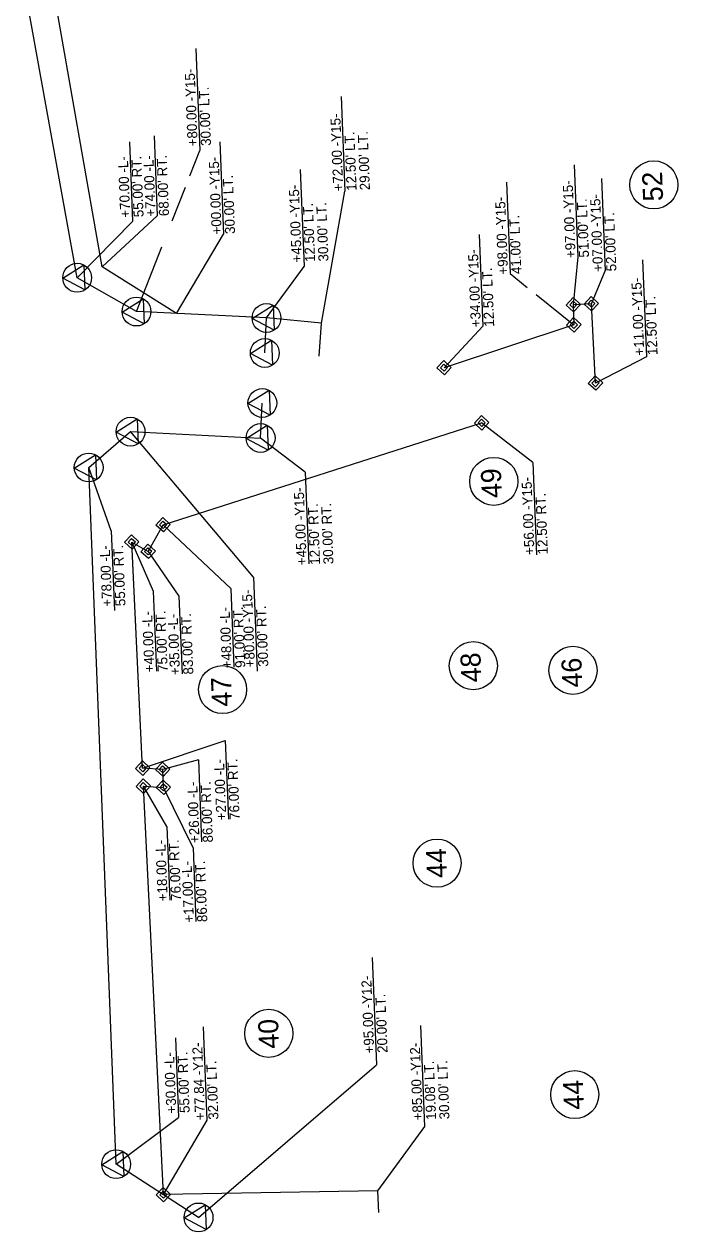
# Model space of a CAD drawing. Extents: x 1627970 to 1628801, y 761752 to 765698.
# Drawn here: x 1628397 to 1628723, y 764572 to 765175 of the extents above; entities that cross this region are included whole.
import ezdxf

# ---------------------------------------------------------------- set-up
doc = ezdxf.new("R2010")
doc.units = 0
for name, color, linetype in [('Exist Property Line Leader', 7, 'Continuous'), ('Exist Property Line Text', 7, 'Continuous'), ('Exist Right of Way Control of Access Line', 7, 'Continuous'), ('Exist Right of Way Monument Leader', 7, 'Continuous'), ('Exist Right of Way Monument Text', 7, 'Continuous'), ('Exist Roads EOT', 7, 'Continuous'), ('Exist Utilities Gas UG Line', 7, 'Continuous'), ('Exist Utilities Gas UG Line Text', 7, 'Continuous'), ('Exist Utilities Other Unknown UG SUE Text', 7, 'Continuous')]:
    doc.layers.add(name, color=color, linetype=linetype)

msp = doc.modelspace()

# ---------------------------------------------------------------- linework, layer by layer
at = {"layer": 'Exist Property Line Leader'}
for p, q in [((1628679.79, 765035.16), (1628670.77, 765034.66)), ((1628670.77, 765034.66), (1628671.03, 765024.62)), ((1628681.86, 764995.53), (1628679.79, 765035.16)), ((1628671.03, 765024.62), (1628606.25, 765003.22)), ((1628625.64, 765023.98), (1628606.25, 765003.22)), ((1628465.98, 764924.84), (1628625.01, 764975.71)), ((1628458.5, 764911.53), (1628465.98, 764924.84)), ((1628455.76, 764803.34), (1628450.31, 764916.21)), ((1628450.31, 764916.21), (1628458.5, 764911.53)), ((1628465.8, 764802.74), (1628455.76, 764803.34)), ((1628466.15, 764793.74), (1628465.8, 764802.74)), ((1628466.1, 764590.44), (1628456.12, 764794.35)), ((1628456.12, 764794.35), (1628466.15, 764793.74))]:
    msp.add_line(p, q, dxfattribs=at)
at = {"layer": 'Exist Property Line Text'}
for p, q in [((1628710.97, 765094.48), (1628710.97, 765094.48)), ((1628631.08, 764946.47), (1628631.08, 764946.47)), ((1628620.87, 764854.47), (1628620.87, 764854.47)), ((1628670.61, 764852.15), (1628670.61, 764852.15)), ((1628495.67, 764842.56), (1628495.67, 764842.56)), ((1628602.74, 764755.93), (1628602.74, 764755.93)), ((1628518.74, 764670.96), (1628518.74, 764670.96)), ((1628671.51, 764640.38), (1628671.51, 764640.38))]:
    msp.add_line(p, q, dxfattribs=at)
for centre in [(1628710.97, 765094.48), (1628631.08, 764946.47), (1628620.87, 764854.47), (1628670.61, 764852.15), (1628495.67, 764842.56), (1628602.74, 764755.93), (1628518.74, 764670.96), (1628671.51, 764640.38)]:
    msp.add_circle(centre, 12, dxfattribs=at)
at = {"layer": 'Exist Right of Way Control of Access Line'}
for p, q in [((1628423.08, 765048.13), (1628396.6, 765194.98)), ((1628452.68, 765031.24), (1628423.08, 765048.13)), ((1628517.6, 765028.05), (1628452.68, 765031.24)), ((1628516.74, 765010.57), (1628517.6, 765028.05)), ((1628514.65, 764968.12), (1628515.51, 764985.6)), ((1628428.83, 764953.4), (1628449.73, 764971.31)), ((1628449.73, 764971.31), (1628514.65, 764968.12)), ((1628442.54, 764605.67), (1628428.83, 764953.4)), ((1628483.68, 764579.07), (1628442.54, 764605.67))]:
    msp.add_line(p, q, dxfattribs=at)
at = {"layer": 'Exist Right of Way Monument Leader'}
for points in [[(1628667.18, 765034.52), (1628670.63, 765038.26), (1628674.37, 765034.8), (1628670.92, 765031.06)], [(1628668.98, 765034.59), (1628670.7, 765036.46), (1628672.57, 765034.73), (1628670.85, 765032.86)], [(1628676.19, 765035.01), (1628679.65, 765038.75), (1628683.38, 765035.3), (1628679.93, 765031.56)], [(1628677.99, 765035.08), (1628679.72, 765036.95), (1628681.59, 765035.23), (1628679.86, 765033.36)], [(1628667.43, 765024.48), (1628670.89, 765028.22), (1628674.63, 765024.76), (1628671.17, 765021.03)], [(1628669.23, 765024.55), (1628670.96, 765026.42), (1628672.83, 765024.69), (1628671.1, 765022.82)], [(1628602.65, 765003.08), (1628606.1, 765006.82), (1628609.84, 765003.36), (1628606.39, 764999.62)], [(1628604.45, 765003.15), (1628606.18, 765005.02), (1628608.04, 765003.29), (1628606.32, 765001.42)], [(1628678.27, 764995.39), (1628681.72, 764999.13), (1628685.46, 764995.68), (1628682.01, 764991.94)], [(1628680.07, 764995.46), (1628681.79, 764997.33), (1628683.66, 764995.6), (1628681.93, 764993.74)], [(1628621.41, 764975.57), (1628624.87, 764979.31), (1628628.61, 764975.85), (1628625.15, 764972.11)], [(1628623.21, 764975.64), (1628624.94, 764977.51), (1628626.81, 764975.78), (1628625.08, 764973.91)], [(1628462.39, 764924.7), (1628465.84, 764928.43), (1628469.58, 764924.98), (1628466.13, 764921.24)], [(1628464.19, 764924.77), (1628465.91, 764926.64), (1628467.78, 764924.91), (1628466.06, 764923.04)], [(1628446.72, 764916.07), (1628450.17, 764919.81), (1628453.91, 764916.36), (1628450.45, 764912.62)], [(1628448.51, 764916.14), (1628450.24, 764918.01), (1628452.11, 764916.28), (1628450.38, 764914.41)], [(1628454.91, 764911.39), (1628458.36, 764915.13), (1628462.1, 764911.67), (1628458.65, 764907.94)], [(1628456.7, 764911.46), (1628458.43, 764913.33), (1628460.3, 764911.6), (1628458.57, 764909.73)], [(1628452.17, 764803.2), (1628455.62, 764806.94), (1628459.36, 764803.48), (1628455.91, 764799.74)], [(1628453.97, 764803.27), (1628455.69, 764805.14), (1628457.56, 764803.41), (1628455.84, 764801.54)], [(1628462.2, 764802.59), (1628465.65, 764806.33), (1628469.39, 764802.88), (1628465.94, 764799.14)], [(1628464, 764802.66), (1628465.72, 764804.53), (1628467.59, 764802.81), (1628465.87, 764800.94)], [(1628452.52, 764794.21), (1628455.98, 764797.94), (1628459.72, 764794.49), (1628456.26, 764790.75)], [(1628454.32, 764794.28), (1628456.05, 764796.15), (1628457.92, 764794.42), (1628456.19, 764792.55)], [(1628462.55, 764793.6), (1628466.01, 764797.34), (1628469.75, 764793.88), (1628466.29, 764790.15)], [(1628464.35, 764793.67), (1628466.08, 764795.54), (1628467.95, 764793.81), (1628466.22, 764791.94)], [(1628462.5, 764590.3), (1628465.95, 764594.04), (1628469.69, 764590.58), (1628466.24, 764586.84)], [(1628464.3, 764590.37), (1628466.02, 764592.24), (1628467.89, 764590.51), (1628466.17, 764588.64)]]:
    msp.add_lwpolyline(points, close=True, dxfattribs=at)
at = {"layer": 'Exist Right of Way Monument Text'}
for p, q in [((1628435.63, 765053.51), (1628402.42, 765242.34)), ((1628472.66, 765030.26), (1628435.63, 765053.51)), ((1628545.08, 765025.42), (1628517.6, 765028.05)), ((1628543.94, 765008.96), (1628545.08, 765025.42)), ((1628573.25, 764592.36), (1628466.1, 764590.44)), ((1628573.65, 764581.45), (1628573.25, 764592.36))]:
    msp.add_line(p, q, dxfattribs=at)
at = {"layer": 'Exist Roads EOT'}
for p, q in [((1628671.15, 765104.52), (1628672.96, 765058.5)), ((1628637.43, 765095.91), (1628639.23, 765050.25)), ((1628684.82, 765097.63), (1628686.63, 765051.62)), ((1628623.84, 765069.65), (1628625.64, 765023.98)), ((1628672.96, 765058.5), (1628670.77, 765034.66)), ((1628679.79, 765035.16), (1628686.63, 765051.62)), ((1628705.35, 765057), (1628707.25, 765008.69)), ((1628639.23, 765050.25), (1628647.82, 765043.33)), ((1628652.25, 765039.76), (1628671.03, 765024.62)), ((1628707.25, 765008.69), (1628681.86, 764995.53)), ((1628650.61, 764955.97), (1628625.01, 764975.71)), ((1628650.61, 764955.97), (1628652.43, 764909.84)), ((1628465.98, 764924.84), (1628499.81, 764893)), ((1628450.31, 764916.21), (1628461.07, 764891.66)), ((1628458.5, 764911.53), (1628473.9, 764889.16)), ((1628461.07, 764891.66), (1628462.65, 764851.72)), ((1628473.9, 764889.16), (1628475.43, 764850.37)), ((1628499.81, 764893), (1628501.36, 764853.7)), ((1628455.76, 764803.34), (1628497.01, 764817.06)), ((1628497.01, 764817.06), (1628498.55, 764777.82)), ((1628483.58, 764807.41), (1628465.8, 764802.74)), ((1628483.58, 764807.41), (1628485.2, 764766.51)), ((1628467.83, 764774.18), (1628456.12, 764794.35)), ((1628480.93, 764763.55), (1628466.15, 764793.74)), ((1628467.83, 764774.18), (1628469.28, 764737.43)), ((1628480.93, 764763.55), (1628482.38, 764726.8)), ((1628488.04, 764627.69), (1628486.13, 764674.23)), ((1628466.1, 764590.44), (1628488.04, 764627.69))]:
    msp.add_line(p, q, dxfattribs=at)
at = {"layer": 'Exist Utilities Gas UG Line'}
for p, q in [((1628482.35, 765162.52), (1628484.35, 765111.71)), ((1628449.14, 765115.9), (1628450.71, 765076.12)), ((1628479.32, 765098.93), (1628484.35, 765111.71)), ((1628534.44, 765102.13), (1628536.35, 765053.75)), ((1628470.53, 765076.59), (1628477.12, 765093.33)), ((1628423.08, 765048.13), (1628450.71, 765076.12)), ((1628452.68, 765031.24), (1628465.4, 765063.55)), ((1628517.6, 765028.05), (1628536.35, 765053.75)), ((1628511.11, 764898.7), (1628449.73, 764971.31)), ((1628536.93, 764951.15), (1628514.65, 764968.12)), ((1628440.08, 764921.73), (1628428.83, 764953.4)), ((1628536.93, 764951.15), (1628538.74, 764905.29)), ((1628440.08, 764921.73), (1628441.65, 764881.95)), ((1628511.11, 764898.7), (1628512.97, 764851.67)), ((1628570.38, 764708.85), (1628572.49, 764655.29)), ((1628472.17, 764668.75), (1628473.74, 764628.97)), ((1628483.68, 764579.07), (1628572.49, 764655.29)), ((1628442.54, 764605.67), (1628473.74, 764628.97))]:
    msp.add_line(p, q, dxfattribs=at)
at = {"layer": 'Exist Utilities Gas UG Line Text'}
for p, q in [((1628554.92, 765138.64), (1628556.78, 765091.4)), ((1628461.46, 765118.97), (1628463.03, 765079.1)), ((1628494.29, 765116.03), (1628496.11, 765069.84)), ((1628545.08, 765025.42), (1628556.78, 765091.4)), ((1628435.63, 765053.51), (1628463.03, 765079.1)), ((1628472.66, 765030.26), (1628496.11, 765069.84)), ((1628596.66, 764624.48), (1628594.6, 764674.8)), ((1628573.25, 764592.36), (1628596.66, 764624.48))]:
    msp.add_line(p, q, dxfattribs=at)
at = {"layer": 'Exist Utilities Other Unknown UG SUE Text'}
for p, q in [((1628423.08, 765048.13), (1628423.08, 765048.13)), ((1628670.77, 765034.66), (1628670.77, 765034.66)), ((1628679.79, 765035.16), (1628679.79, 765035.16)), ((1628452.68, 765031.24), (1628452.68, 765031.24)), ((1628517.6, 765028.05), (1628517.6, 765028.05)), ((1628671.03, 765024.62), (1628671.03, 765024.62)), ((1628516.74, 765010.57), (1628516.74, 765010.57)), ((1628606.25, 765003.22), (1628606.25, 765003.22)), ((1628681.86, 764995.53), (1628681.86, 764995.53)), ((1628515.51, 764985.6), (1628515.51, 764985.6)), ((1628625.01, 764975.71), (1628625.01, 764975.71)), ((1628449.73, 764971.31), (1628449.73, 764971.31)), ((1628514.65, 764968.12), (1628514.65, 764968.12)), ((1628428.83, 764953.4), (1628428.83, 764953.4)), ((1628465.98, 764924.84), (1628465.98, 764924.84)), ((1628450.31, 764916.21), (1628450.31, 764916.21)), ((1628458.5, 764911.53), (1628458.5, 764911.53)), ((1628455.76, 764803.34), (1628455.76, 764803.34)), ((1628465.8, 764802.74), (1628465.8, 764802.74)), ((1628456.12, 764794.35), (1628456.12, 764794.35)), ((1628466.15, 764793.74), (1628466.15, 764793.74)), ((1628442.54, 764605.67), (1628442.54, 764605.67)), ((1628466.1, 764590.44), (1628466.1, 764590.44)), ((1628483.68, 764579.07), (1628483.68, 764579.07))]:
    msp.add_line(p, q, dxfattribs=at)
for points in [[(1628415.88, 765047.86), (1628426.44, 765054.5), (1628426.93, 765042.03)], [(1628445.47, 765030.97), (1628456.04, 765037.61), (1628456.53, 765025.14)], [(1628510.39, 765027.78), (1628520.96, 765034.41), (1628521.45, 765021.95)], [(1628509.53, 765010.3), (1628520.1, 765016.94), (1628520.59, 765004.47)], [(1628508.31, 764985.33), (1628518.87, 764991.97), (1628519.36, 764979.5)], [(1628442.53, 764971.04), (1628453.09, 764977.68), (1628453.58, 764965.21)], [(1628507.45, 764967.85), (1628518.01, 764974.49), (1628518.5, 764962.02)], [(1628421.62, 764953.13), (1628432.19, 764959.76), (1628432.68, 764947.3)], [(1628435.33, 764605.4), (1628445.9, 764612.04), (1628446.39, 764599.57)], [(1628476.47, 764578.8), (1628487.04, 764585.44), (1628487.53, 764572.97)]]:
    msp.add_lwpolyline(points, close=True, dxfattribs=at)
for centre in [(1628423.08, 765048.13), (1628452.68, 765031.24), (1628517.6, 765028.05), (1628516.74, 765010.57), (1628515.51, 764985.6), (1628449.73, 764971.31), (1628514.65, 764968.12), (1628428.83, 764953.4), (1628442.54, 764605.67), (1628483.68, 764579.07)]:
    msp.add_circle(centre, 7.2, dxfattribs=at)

# ---------------------------------------------------------------- texts
at = {"layer": 'Exist Property Line Text'}
for s, p in [('52', (1628715.65, 765086.45)), ('49', (1628635.14, 764938.33)), ('48', (1628624.94, 764846.33)), ('46', (1628675.35, 764843.76)), ('47', (1628500.4, 764834.17)), ('44', (1628607.74, 764748.65)), ('40', (1628523.92, 764663.47)), ('44', (1628676.09, 764632.99))]:
    msp.add_text(s, height=10, rotation=92.25819, dxfattribs=at).set_placement(p)
at = {"layer": 'Exist Roads EOT'}
for s, p in [('+97.00 -Y15-', (1628671.98, 765058.03)), ('+98.00 -Y15-', (1628638.24, 765049.77)), ('+07.00 -Y15-', (1628685.64, 765051.15)), ("51.00' LT.", (1628678.64, 765058.29)), ("41.00' LT.", (1628644.9, 765050.04)), ("52.00' LT.", (1628692.31, 765051.41)), ('+34.00 -Y15-', (1628624.65, 765023.51)), ("12.50' LT.", (1628631.31, 765023.77)), ('+11.00 -Y15-', (1628706.22, 765009.37)), ("12.50' LT.", (1628712.88, 765009.63)), ('+56.00 -Y15-', (1628651.42, 764909.88)), ("12.50' RT.", (1628658.08, 764910.14)), ('+48.00 -L-', (1628500.37, 764853.22)), ("91.00' RT.", (1628507.04, 764853.49)), ('+40.00 -L-', (1628461.66, 764851.24)), ("75.00' RT.", (1628468.32, 764851.5)), ('+35.00 -L-', (1628474.44, 764849.89)), ("83.00' RT.", (1628481.1, 764850.16)), ('+27.00 -L-', (1628497.57, 764777.34)), ("76.00' RT.", (1628504.23, 764777.61)), ('+26.00 -L-', (1628484.21, 764766.03)), ("86.00' RT.", (1628490.87, 764766.3)), ('+18.00 -L-', (1628468.29, 764736.95)), ("76.00' RT.", (1628474.96, 764737.21)), ('+17.00 -L-', (1628481.39, 764726.32)), ("86.00' RT.", (1628488.05, 764726.58)), ('+77.84 -Y12-', (1628486.98, 764627.7)), ("32.00' LT.", (1628493.64, 764627.96))]:
    msp.add_text(s, height=5, rotation=92.25819, dxfattribs=at).set_placement(p)
at = {"layer": 'Exist Utilities Gas UG Line'}
for s, p in [('+80.00 -Y15-', (1628483.24, 765113.78)), ("30.00' LT.", (1628489.91, 765114.04)), ('+70.00 -L-', (1628449.6, 765078.19)), ("55.00' RT.", (1628456.26, 765078.45)), ('+45.00 -Y15-', (1628535.24, 765055.82)), ("12.50' LT.", (1628541.9, 765056.08)), ("30.00' LT.", (1628548.56, 765056.34)), ('+45.00 -Y15-', (1628537.73, 764904.69)), ("12.50' RT.", (1628544.39, 764904.96)), ("30.00' RT.", (1628551.05, 764905.22)), ('+78.00 -L-', (1628440.54, 764884.02)), ("55.00' RT.", (1628447.2, 764884.28)), ('+80.00 -Y15-', (1628511.86, 764853.73)), ("30.00' RT.", (1628518.52, 764853.99)), ('+95.00 -Y12-', (1628571.4, 764661.02)), ("20.00' LT.", (1628578.06, 764661.29)), ('+30.00 -L-', (1628472.63, 764631.03)), ("55.00' RT.", (1628479.29, 764631.29))]:
    msp.add_text(s, height=5, rotation=92.25819, dxfattribs=at).set_placement(p)
at = {"layer": 'Exist Utilities Gas UG Line Text'}
for s, p in [('+72.00 -Y15-', (1628555.95, 765091.37)), ("12.50' LT.", (1628562.61, 765091.63)), ("29.00' LT.", (1628569.27, 765091.89)), ('+74.00 -L-', (1628462.29, 765078.69)), ("68.00' RT.", (1628468.95, 765078.95)), ('+00.00 -Y15-', (1628495.27, 765069.8)), ("30.00' LT.", (1628501.93, 765070.07)), ('+85.00 -Y12-', (1628595.65, 764627.59)), ("19.08' LT.", (1628602.31, 764627.85)), ("30.00' LT.", (1628608.97, 764628.11))]:
    msp.add_text(s, height=5, rotation=92.25819, dxfattribs=at).set_placement(p)

doc.saveas('drawing.dxf')
